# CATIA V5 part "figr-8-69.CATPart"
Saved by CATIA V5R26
Part number: Part1
Bounding box of the stored display mesh (mm): x -75 to 75, y -65.851 to 65.851, z 0 to 50
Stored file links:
  D:\_Deepak\CATIA\CATIA V5-6R2016_Deepak\Resources\Part files\Partfiles\c08_catia_v5_6r2016_prt\figr-8-69.CATPart
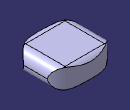
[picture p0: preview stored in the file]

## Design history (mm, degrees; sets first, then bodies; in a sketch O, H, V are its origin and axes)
Body1 (main body)
  Sketch1 on xy-plane, origin (0, 0, 0), H (1, 0, 0), V (0, 1, 0)
    line L1 (-75, 75) -> (75, 75)
    line L2 (75, 75) -> (75, -75)
    line L3 (75, -75) -> (-75, -75)
    line L4 (-75, -75) -> (-75, 75)
    axis line L5 (75, -75) -> (-75, 75)
    length L3 = 150
    length L2 = 150
    horizontal: L1 H, L3 H
    vertical: L2 V, L4 V
    midpoint: O L5
  Pad1: profile Sketch1, direction (0, 0, 1), length 50
  Fillet1: radius 25, on face of Pad1 (x6)
  Body2
    Sketch2 on xy-plane, origin (0, 0, 0), H (1, 0, 0), V (0, 1, 0)
      ellipse A1 centre (0, 0) semi-axes 84.7617, 65.8627 rotation 0
      point P1 (84.7617, 0)
      point P2 (0, 65.8627)
      coincidence: P1 H, P2 V, A1 P1, A1 P2
    Pad2: profile Sketch2, direction (0, 0, 1), length 50
  Intersect1: tool Body2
